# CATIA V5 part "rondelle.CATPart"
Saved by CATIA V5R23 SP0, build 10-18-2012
Part number: rondelle
Bounding box of the stored display mesh (mm): x -9 to 9, y -8.951 to 8.951, z 0 to 5
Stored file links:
  C:\wamp\www\COURS\CONCEPTION GMP1\TITRE 01-CATIA VOLUMIQUE\05--ACTIONNEUR DE VANNE\prof\CORRECTION\Assemblage\rondelle.CATPart
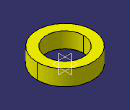
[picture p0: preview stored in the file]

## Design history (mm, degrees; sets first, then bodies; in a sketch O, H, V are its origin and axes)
Body1 (main body)
  Sketch1 on xy-plane, origin (0, 0, 0), H (1, 0, 0), V (0, 1, 0)
    circle A1 centre (0, 0) radius 9
    circle A2 centre (0, 0) radius 6
    radius A2 = 6
    radius A1 = 9
  Pad1: profile Sketch1, direction (0, 0, 1), length 5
